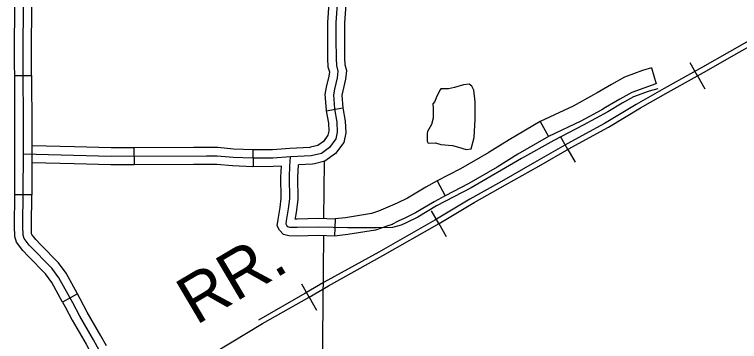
# Model space of a CAD drawing. Extents: x 8749 to 11879, y 13275 to 15339.
# Drawn here: x 10150.4 to 10278.9, y 13555.1 to 13613 of the extents above; entities that cross this region are included whole.
import ezdxf

# ---------------------------------------------------------------- set-up
doc = ezdxf.new("R2010")
doc.units = 0
for name, color, linetype in [('Level 15', 7, 'Continuous'), ('Level 31', 7, 'Continuous'), ('Level 32', 7, 'Continuous'), ('Level 35', 7, 'Continuous'), ('Level 40', 7, 'Continuous'), ('Level 45', 7, 'Continuous'), ('Level 46', 7, 'Continuous'), ('Level 5', 7, 'Continuous')]:
    doc.layers.add(name, color=color, linetype=linetype)

msp = doc.modelspace()

# ---------------------------------------------------------------- linework, layer by layer
at = {"layer": 'Level 15'}
msp.add_lwpolyline([(10165.41, 13540.78), (10194.35, 13558.24), (10202.59, 13562.93), (10206.03, 13564.94), (10215.63, 13570.28), (10225.65, 13575.96), (10231.85, 13579.64), (10237.39, 13582.78), (10243.27, 13586.12), (10249.04, 13589.41), (10255.65, 13593.03), (10261.29, 13596.42), (10266.23, 13599.22), (10270.9, 13601.81), (10273.02, 13603), (10277.84, 13605.76), (10282.05, 13608.14)], dxfattribs=at)
at = {"layer": 'Level 31'}
for p, q in [((10150.43, 13602.13), (10153.43, 13602.15)), ((10153.44, 13581.01), (10150.44, 13581.03)), ((10161.54, 13563.5), (10158.92, 13562.05))]:
    msp.add_line(p, q, dxfattribs=at)
for points in [[(10150.47, 13612.7), (10150.47, 13623.26)], [(10153.47, 13612.7), (10153.47, 13623.26)], [(10207.97, 13623.01), (10208.16, 13620.55), (10208.19, 13619.41), (10208.08, 13618.27), (10207.79, 13617.1), (10207.64, 13615.77), (10207.35, 13611.47), (10207.35, 13608.61), (10207.38, 13605.19), (10207.42, 13603.9), (10207.7, 13602.92)], [(10150.43, 13602.13), (10150.42, 13604.06), (10150.42, 13608.95), (10150.47, 13612.21), (10150.47, 13612.7)], [(10153.43, 13602.15), (10153.42, 13604.06), (10153.42, 13608.93), (10153.47, 13612.19), (10153.47, 13612.7)], [(10207.7, 13602.92), (10207.59, 13601.75), (10207.08, 13599.76), (10206.89, 13598.73), (10207.08, 13596.23), (10207.52, 13593.88), (10207.59, 13592.15), (10207.33, 13590.94), (10206.2, 13589.4), (10204.76, 13588.37), (10202.96, 13587.93), (10199.28, 13587.73)], [(10150.47, 13591.58), (10150.47, 13592.82), (10150.43, 13602.13)], [(10153.43, 13602.15), (10153.47, 13592.83), (10153.47, 13591.58)], [(10150.44, 13581.03), (10150.44, 13581.56), (10150.47, 13588.23), (10150.47, 13591.58)], [(10153.47, 13591.58), (10153.47, 13588.22), (10153.44, 13581.54), (10153.44, 13581.01)], [(10186.33, 13587.9), (10184.44, 13587.9), (10167.51, 13587.84), (10151.97, 13588.22)], [(10199.28, 13587.73), (10196.17, 13587.52), (10192.64, 13587.49), (10189.12, 13587.63), (10186.33, 13587.9)], [(10152.88, 13570.12), (10151.86, 13571.16), (10150.76, 13572.63), (10150.45, 13573.65), (10150.39, 13575.49), (10150.44, 13581.03)], [(10155.02, 13572.22), (10154.15, 13573.11), (10153.47, 13574.01), (10153.43, 13574.14), (10153.39, 13575.52), (10153.44, 13581.01)], [(10161.54, 13563.5), (10159.53, 13567.14), (10158.17, 13569), (10155.02, 13572.22)], [(10158.92, 13562.05), (10156.99, 13565.52), (10155.87, 13567.06), (10152.88, 13570.12)], [(10166.68, 13554.27), (10165.69, 13556.08), (10163.27, 13560.26), (10162.04, 13562.62), (10161.54, 13563.5)], [(10158.92, 13562.05), (10159.39, 13561.2), (10160.64, 13558.81), (10163.07, 13554.61), (10164.04, 13552.83)]]:
    msp.add_lwpolyline(points, dxfattribs=at)
at = {"layer": 'Level 32'}
for points in [[(10151.97, 13588.22), (10151.97, 13592.82), (10151.92, 13604.06), (10151.92, 13608.94), (10151.97, 13612.2), (10151.97, 13623.44), (10152.02, 13633.07)], [(10151.94, 13573.9), (10151.89, 13575.5), (10151.94, 13581.55), (10151.97, 13588.22)], [(10168.55, 13547.67), (10167.85, 13549), (10164.38, 13555.34), (10161.95, 13559.53), (10160.71, 13561.91), (10158.26, 13566.33), (10157.02, 13568.03), (10153.01, 13572.13), (10152.12, 13573.32), (10151.94, 13573.9)]]:
    msp.add_lwpolyline(points, dxfattribs=at)
at = {"layer": 'Level 35'}
msp.add_lwpolyline([(10223.68, 13590.15), (10224.97, 13590.25), (10225.91, 13589.92), (10228.01, 13589.76), (10229.09, 13589.44), (10230.44, 13589.06), (10231.3, 13589.17), (10231.84, 13591.16), (10232, 13594.4), (10232, 13597.5), (10231.76, 13599.53), (10231.41, 13600.28), (10230.98, 13600.61), (10229.93, 13600.53), (10228.34, 13600.01), (10227.31, 13599.77), (10226.64, 13599.77), (10225.94, 13599.8), (10225.8, 13599.61), (10225.53, 13599.1), (10225.13, 13598.18), (10224.86, 13597.53), (10224.54, 13597.13), (10224.56, 13596.37), (10224.56, 13594.62), (10224.29, 13593.48), (10223.59, 13592.22), (10223.54, 13591.86), (10223.49, 13591.24), (10223.49, 13590.54), (10223.68, 13590.15)], dxfattribs=at)
at = {"layer": 'Level 40'}
for p, q in [((10271.41, 13602.09), (10270.12, 13604.39)), ((10271.41, 13602.09), (10272.71, 13599.79)), ((10248.45, 13589.08), (10247.14, 13591.37)), ((10248.45, 13589.08), (10249.76, 13586.78)), ((10225.56, 13575.92), (10224.26, 13578.21)), ((10225.56, 13575.92), (10226.87, 13573.62)), ((10202.58, 13562.92), (10201.28, 13565.22)), ((10202.58, 13562.92), (10203.89, 13560.63))]:
    msp.add_line(p, q, dxfattribs=at)
msp.add_lwpolyline([(10165.41, 13540.78), (10194.35, 13558.24), (10202.59, 13562.93), (10206.03, 13564.94), (10215.63, 13570.28), (10225.65, 13575.96), (10231.85, 13579.64), (10237.39, 13582.78), (10243.27, 13586.12), (10249.04, 13589.41), (10255.65, 13593.03), (10261.29, 13596.42), (10266.23, 13599.22), (10270.9, 13601.81), (10273.02, 13603), (10277.84, 13605.76), (10282.05, 13608.14)], dxfattribs=at)
at = {"layer": 'Level 45'}
for p, q in [((10263.29, 13603.49), (10264.1, 13600.7)), ((10205.62, 13595.87), (10208.57, 13596.43)), ((10243.54, 13593.99), (10245, 13591.36)), ((10171.56, 13589.36), (10171.57, 13586.36)), ((10192.65, 13588.99), (10192.68, 13585.99)), ((10225.3, 13583.48), (10226.7, 13580.82)), ((10207.19, 13576.73), (10207.11, 13573.73))]:
    msp.add_line(p, q, dxfattribs=at)
for points in [[(10206.34, 13617.48), (10206.31, 13617.36), (10206.15, 13615.91), (10205.85, 13611.52), (10205.85, 13608.6), (10205.87, 13606.56)], [(10209.27, 13616.83), (10209.14, 13615.64), (10208.85, 13611.42), (10208.85, 13608.61), (10208.87, 13606.59)], [(10205.87, 13606.56), (10205.88, 13605.16), (10205.93, 13603.67), (10206.18, 13602.78), (10206.11, 13602.01), (10205.61, 13600.08), (10205.38, 13598.81), (10205.59, 13596.04), (10205.62, 13595.87)], [(10208.87, 13606.59), (10208.88, 13605.22), (10208.92, 13604.13), (10209.22, 13603.06), (10209.07, 13601.49), (10208.54, 13599.44), (10208.4, 13598.66), (10208.57, 13596.43), (10208.57, 13596.43)], [(10263.29, 13603.49), (10261.67, 13603.01), (10258.5, 13601.87), (10256.17, 13600.56), (10253.62, 13599.07), (10253, 13598.73)], [(10264.02, 13600.67), (10259.75, 13599.14), (10257.67, 13597.96), (10255.1, 13596.46), (10254.44, 13596.09)], [(10264.36, 13599.8), (10262.86, 13599.36), (10260.1, 13598.37), (10258.08, 13597.23), (10255.51, 13595.72), (10251.14, 13593.34), (10245.96, 13590.62), (10240.24, 13587.45), (10231.28, 13582.29), (10225.15, 13579.06), (10221.85, 13577.07), (10219.79, 13576.04), (10218.93, 13575.68), (10217.38, 13575.27), (10214.56, 13575.16), (10209.45, 13575.16), (10204.27, 13575.31), (10200.49, 13575.23), (10199.2, 13575.27), (10198.84, 13575.34), (10198.62, 13575.6), (10198.51, 13575.82), (10198.58, 13576.45), (10198.95, 13578.54), (10199.17, 13580.34), (10199.09, 13584.2), (10199.2, 13586.08), (10199.28, 13587.73)], [(10253, 13598.73), (10249.38, 13596.75), (10243.54, 13593.99)], [(10208.57, 13596.43), (10209.01, 13594.05), (10209.1, 13592.03), (10208.73, 13590.31), (10207.26, 13588.32), (10205.4, 13586.98), (10203.56, 13586.53)], [(10205.62, 13595.87), (10206.02, 13593.71), (10206.08, 13592.28), (10205.93, 13591.57), (10205.13, 13590.48), (10204.12, 13589.76), (10202.85, 13589.44)], [(10254.44, 13596.09), (10250.75, 13594.08), (10245, 13591.36)], [(10243.54, 13593.98), (10238.02, 13590.78), (10234.32, 13588.47)], [(10245, 13591.36), (10239.56, 13588.21), (10235.91, 13585.93)], [(10161.04, 13589.5), (10153.47, 13589.69)], [(10171.56, 13589.36), (10167.52, 13589.34), (10161.04, 13589.5)], [(10182.12, 13589.39), (10171.56, 13589.36)], [(10192.67, 13588.99), (10189.22, 13589.13), (10186.4, 13589.4), (10184.43, 13589.4), (10182.12, 13589.39)], [(10202.85, 13589.44), (10202.74, 13589.42), (10199.19, 13589.23), (10196.11, 13589.02), (10192.65, 13588.99)], [(10234.41, 13588.53), (10229.43, 13585.65), (10225.3, 13583.48)], [(10160.97, 13586.5), (10153.46, 13586.69)], [(10171.57, 13586.36), (10167.49, 13586.34), (10160.97, 13586.5)], [(10182.13, 13586.39), (10171.57, 13586.36)], [(10192.68, 13585.99), (10192.62, 13585.99), (10189.02, 13586.14), (10186.26, 13586.4), (10184.44, 13586.4), (10182.13, 13586.39)], [(10197.7, 13586.12), (10196.23, 13586.02), (10192.68, 13585.99)], [(10197.28, 13577.71), (10197.46, 13578.76), (10197.67, 13580.42), (10197.59, 13584.23), (10197.7, 13586.12)], [(10200.23, 13577.19), (10200.43, 13578.32), (10200.67, 13580.27), (10200.59, 13584.17), (10200.72, 13586.31)], [(10203.56, 13586.53), (10203.18, 13586.44), (10200.72, 13586.31)], [(10235.91, 13585.93), (10230.88, 13583.03), (10226.7, 13580.82)], [(10225.3, 13583.48), (10223.27, 13582.4), (10220, 13580.44), (10218.18, 13579.53), (10214.86, 13578.12)], [(10226.7, 13580.82), (10224.74, 13579.79), (10221.44, 13577.81), (10219.44, 13576.81), (10218.5, 13576.41), (10217.13, 13575.69)], [(10207.11, 13573.73), (10204.27, 13573.81), (10200.48, 13573.73), (10199.03, 13573.78), (10198.03, 13573.98), (10197.36, 13574.77), (10196.96, 13575.55), (10197.09, 13576.66), (10197.28, 13577.71)], [(10207.19, 13576.73), (10204.28, 13576.81), (10200.5, 13576.73), (10200.15, 13576.74), (10200.23, 13577.19)], [(10214.86, 13578.12), (10213.65, 13577.72), (10209.07, 13576.95), (10207.19, 13576.75)], [(10217.35, 13575.78), (10216.73, 13575.58), (10214.37, 13574.79), (10209.47, 13573.98), (10207.11, 13573.73)]]:
    msp.add_lwpolyline(points, dxfattribs=at)
at = {"layer": 'Level 46'}
for points in [[(10334.95, 13639.23), (10332.42, 13637.84), (10329.95, 13636.4), (10326.1, 13634.2), (10321.26, 13631.37), (10316.26, 13628.58), (10312.7, 13626.59), (10310.06, 13625.05), (10305.23, 13622.34), (10299.39, 13619.03), (10295.57, 13616.87), (10293.66, 13615.8), (10289.8, 13613.56), (10286.66, 13611.78), (10281.33, 13608.76), (10277.11, 13606.37), (10272.3, 13603.62), (10270.2, 13602.44), (10265.52, 13599.85), (10260.53, 13597.02), (10254.91, 13593.64), (10248.34, 13590.05), (10242.54, 13586.74), (10236.66, 13583.4)], [(10236.66, 13583.4), (10231.1, 13580.24), (10224.89, 13576.56), (10214.92, 13570.9), (10205.29, 13565.55), (10201.84, 13563.53), (10193.63, 13558.86)]]:
    msp.add_lwpolyline(points, dxfattribs=at)
at = {"layer": 'Level 5'}
for points in [[(10205.25, 13586.94), (10205.16, 13576.78)], [(10205.14, 13573.78), (10204.93, 13549.75)]]:
    msp.add_lwpolyline(points, dxfattribs=at)

# ---------------------------------------------------------------- texts
at = {"layer": 'Level 40'}
msp.add_text('RR.', height=8.448, rotation=30.6048, dxfattribs=at).set_placement((10182.55, 13557.86))

doc.saveas('drawing.dxf')
